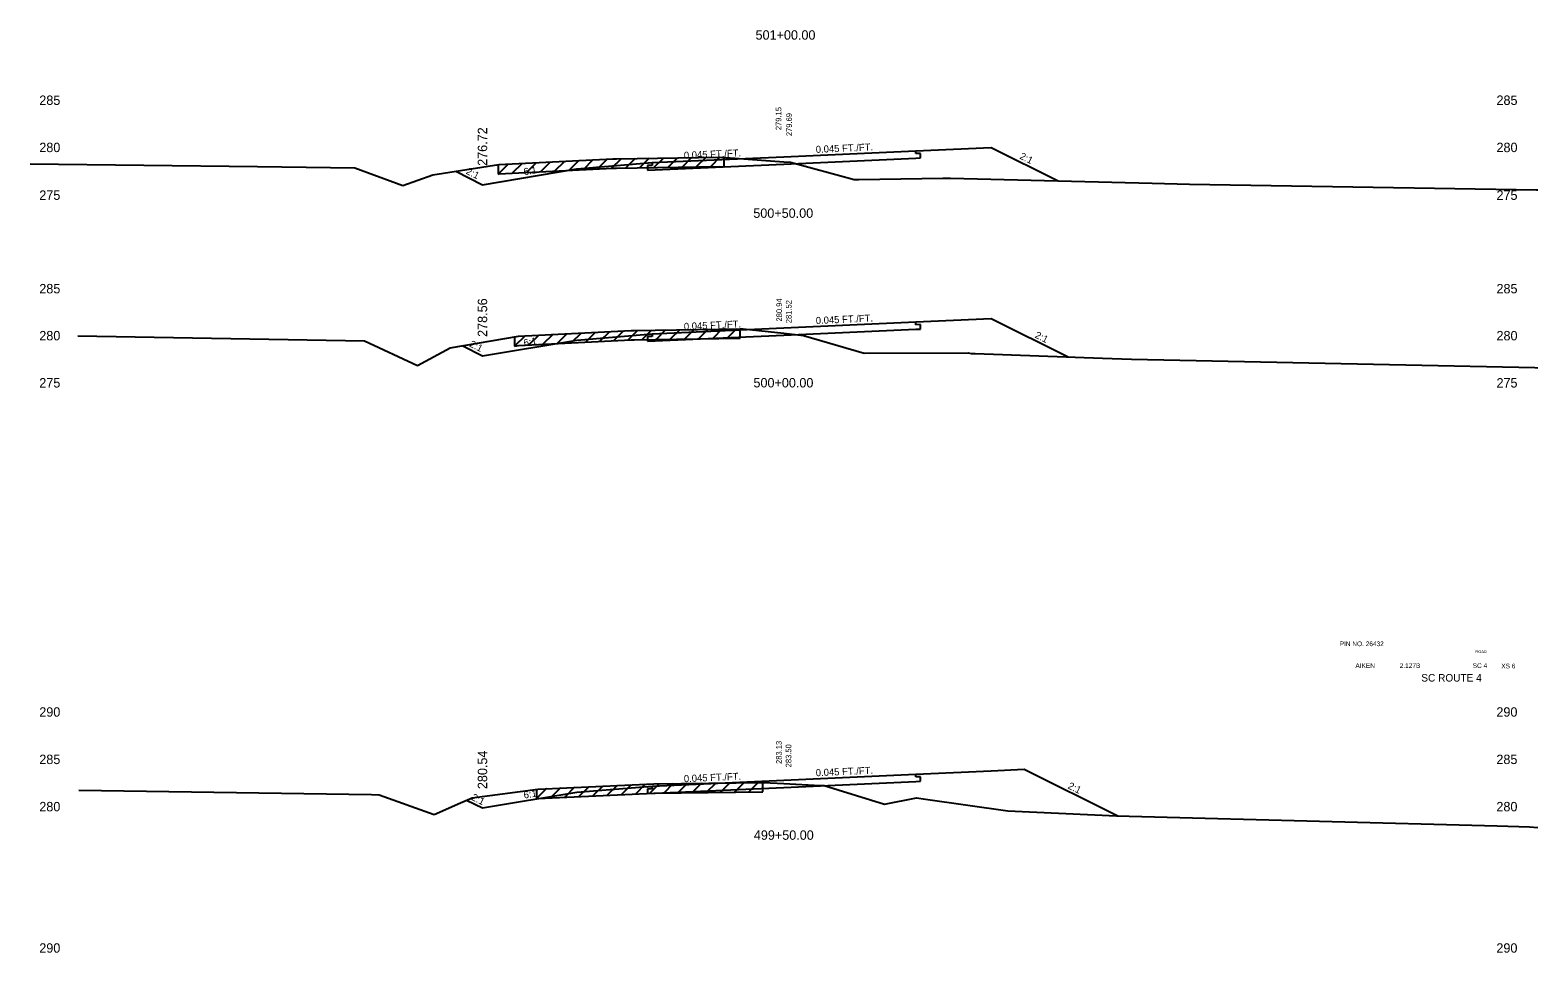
# Model space of a CAD drawing. Extents: x 883 to 1160, y 1002 to 4323.
# Drawn here: x 1000 to 1160, y 1645.2 to 1743.1 of the extents above; entities that cross this region are included whole.
import ezdxf

# ---------------------------------------------------------------- set-up
doc = ezdxf.new("R2010")
doc.units = 0
for name, color, linetype in [('Level 1', 7, 'Continuous'), ('Level 10', 7, 'Continuous'), ('Level 11', 7, 'Continuous'), ('Level 12', 7, 'Continuous'), ('Level 3', 7, 'Continuous'), ('Level 32', 7, 'Continuous'), ('Level 33', 7, 'Continuous'), ('Level 59', 7, 'Continuous'), ('Level 6', 7, 'Continuous'), ('Level 60', 7, 'Continuous'), ('Level 61', 7, 'Continuous'), ('Level 7', 7, 'Continuous')]:
    doc.layers.add(name, color=color, linetype=linetype)

msp = doc.modelspace()

# ---------------------------------------------------------------- linework, layer by layer
at = {"layer": 'Level 11'}
for p, q in [((1094, 1730.02), (1094, 1730.32)), ((1094.5, 1730.04), (1094, 1730.02)), ((1094.5, 1729.56), (1094.5, 1730.04)), ((1094, 1729.54), (1094.5, 1729.56)), ((1094, 1711.85), (1094, 1712.15)), ((1094.5, 1711.87), (1094, 1711.85)), ((1094, 1711.37), (1094.5, 1711.39)), ((1094.5, 1711.39), (1094.5, 1711.87)), ((1094, 1663.83), (1094, 1664.13)), ((1094.5, 1663.85), (1094, 1663.83)), ((1094, 1663.35), (1094.5, 1663.37)), ((1094.5, 1663.37), (1094.5, 1663.85))]:
    msp.add_line(p, q, dxfattribs=at)
at = {"layer": 'Level 12'}
for p, q in [((1065.5, 1728.28), (1080, 1728.91)), ((1066, 1728.76), (1065.5, 1728.76)), ((1065.5, 1728.76), (1065.5, 1728.28)), ((1066, 1729.06), (1066, 1728.76)), ((1080, 1728.91), (1094, 1729.54)), ((1065.5, 1710.11), (1080, 1710.74)), ((1066, 1710.59), (1065.5, 1710.59)), ((1065.5, 1710.59), (1065.5, 1710.11)), ((1066, 1710.89), (1066, 1710.59)), ((1080, 1710.74), (1094, 1711.37)), ((1065.5, 1662.09), (1080, 1662.72)), ((1066, 1662.57), (1065.5, 1662.57)), ((1065.5, 1662.57), (1065.5, 1662.09)), ((1066, 1662.87), (1066, 1662.57)), ((1080, 1662.72), (1094, 1663.35))]:
    msp.add_line(p, q, dxfattribs=at)
at = {"layer": 'Level 59'}
for p, q in [((1066, 1729.06), (1080, 1729.69)), ((1080, 1729.69), (1094, 1730.32)), ((1080, 1711.52), (1094, 1712.15)), ((1066, 1710.89), (1080, 1711.52)), ((1080, 1663.5), (1094, 1664.13)), ((1066, 1662.87), (1080, 1663.5))]:
    msp.add_line(p, q, dxfattribs=at)
at = {"layer": 'Level 6'}
for p, q in [((1094, 1730.32), (1102, 1730.68)), ((1058, 1728.39), (1066, 1729.06)), ((1094, 1712.15), (1102, 1712.51)), ((1058, 1710.22), (1066, 1710.89)), ((1094, 1664.13), (1102, 1664.49)), ((1102, 1664.49), (1105.5, 1664.65)), ((1058, 1662.2), (1066, 1662.87))]:
    msp.add_line(p, q, dxfattribs=at)
at = {"layer": 'Level 60'}
for p, q in [((1062.22, 1729.47), (1073.11, 1729.64)), ((1073.11, 1729.64), (1073.81, 1729.62)), ((1073.81, 1729.62), (1080, 1729.15)), ((1000, 1728.92), (1024.13, 1728.65)), ((1024.13, 1728.65), (1034.44, 1728.51)), ((1034.44, 1728.51), (1039.55, 1726.65)), ((1042.74, 1727.76), (1049.73, 1728.86)), ((1049.73, 1728.86), (1061.84, 1729.46)), ((1061.84, 1729.46), (1062.22, 1729.47)), ((1080, 1729.15), (1080.68, 1729.1)), ((1080.68, 1729.1), (1087.44, 1727.28)), ((1039.55, 1726.65), (1042.74, 1727.76)), ((1087.44, 1727.28), (1087.94, 1727.28)), ((1087.94, 1727.28), (1096.85, 1727.43)), ((1096.85, 1727.43), (1097.68, 1727.4)), ((1097.68, 1727.4), (1119.07, 1726.88)), ((1119.07, 1726.88), (1123.03, 1726.79)), ((1123.03, 1726.79), (1159.87, 1726.19)), ((1159.87, 1726.19), (1160, 1726.18)), ((1005.06, 1710.68), (1035.47, 1710.13)), ((1044.57, 1709.38), (1051.82, 1710.65)), ((1051.82, 1710.65), (1063.78, 1711.23)), ((1063.78, 1711.23), (1064.1, 1711.24)), ((1064.1, 1711.24), (1075.33, 1711.43)), ((1075.33, 1711.43), (1075.66, 1711.43)), ((1075.66, 1711.43), (1080, 1710.94)), ((1080, 1710.94), (1082.07, 1710.72)), ((1082.07, 1710.72), (1088.5, 1708.83)), ((1035.47, 1710.13), (1041.1, 1707.53)), ((1041.1, 1707.53), (1044.57, 1709.38)), ((1088.5, 1708.83), (1099.56, 1708.86)), ((1099.56, 1708.86), (1099.86, 1708.81)), ((1099.86, 1708.81), (1100.3, 1708.79)), ((1100.3, 1708.79), (1113.79, 1708.29)), ((1113.79, 1708.29), (1116.87, 1708.21)), ((1116.87, 1708.21), (1159.68, 1707.3)), ((1159.68, 1707.3), (1160, 1707.29)), ((1005.18, 1662.44), (1036.24, 1661.97)), ((1046.89, 1661.63), (1053.87, 1662.55)), ((1053.87, 1662.55), (1066.19, 1663.11)), ((1066.19, 1663.11), (1077.82, 1663.24)), ((1077.82, 1663.24), (1080, 1663.13)), ((1080, 1663.13), (1083.84, 1662.93)), ((1083.84, 1662.93), (1084.25, 1662.91)), ((1084.25, 1662.91), (1090.66, 1660.94)), ((1036.24, 1661.97), (1037.05, 1661.95)), ((1037.05, 1661.95), (1042.87, 1659.86)), ((1042.87, 1659.86), (1045.68, 1661.1)), ((1045.68, 1661.1), (1046.89, 1661.63)), ((1090.66, 1660.94), (1094.06, 1661.6)), ((1094.06, 1661.6), (1095.01, 1661.49)), ((1095.01, 1661.49), (1103.74, 1660.25)), ((1103.74, 1660.25), (1115.3, 1659.69)), ((1115.3, 1659.69), (1117.98, 1659.63)), ((1117.98, 1659.63), (1155.69, 1658.65)), ((1155.69, 1658.65), (1159.12, 1658.54)), ((1159.12, 1658.54), (1160, 1658.46))]:
    msp.add_line(p, q, dxfattribs=at)
at = {"layer": 'Level 61'}
for p, q in [((1071.7, 1729.62), (1070.69, 1728.61)), ((1073.2, 1729.64), (1072.19, 1728.63)), ((1073.64, 1728.63), (1073.64, 1729.63)), ((1050.72, 1728.91), (1049.65, 1727.85)), ((1049.65, 1728.85), (1049.65, 1727.85)), ((1049.73, 1727.86), (1061.84, 1728.46)), ((1052.21, 1728.98), (1051.16, 1727.93)), ((1053.71, 1729.05), (1052.66, 1728)), ((1055.21, 1729.13), (1054.16, 1728.08)), ((1056.72, 1729.2), (1055.66, 1728.15)), ((1058.22, 1729.28), (1057.17, 1728.23)), ((1059.72, 1729.35), (1058.67, 1728.3)), ((1061.22, 1729.43), (1060.17, 1728.37)), ((1062.71, 1729.48), (1061.67, 1728.45)), ((1061.84, 1728.46), (1062.22, 1728.47)), ((1062.22, 1728.47), (1073.11, 1728.64)), ((1064.19, 1729.5), (1063.17, 1728.49)), ((1065.69, 1729.53), (1064.68, 1728.51)), ((1067.2, 1729.55), (1066.18, 1728.54)), ((1068.7, 1729.57), (1067.68, 1728.56)), ((1070.2, 1729.6), (1069.18, 1728.58)), ((1073.11, 1728.64), (1073.64, 1728.63)), ((1049.65, 1727.85), (1049.73, 1727.86)), ((1052.52, 1710.68), (1051.41, 1709.58)), ((1051.41, 1710.58), (1051.41, 1709.58)), ((1053.97, 1710.75), (1052.91, 1709.7)), ((1055.47, 1710.82), (1054.41, 1709.77)), ((1056.97, 1710.9), (1055.92, 1709.85)), ((1058.47, 1710.97), (1057.42, 1709.92)), ((1059.97, 1711.04), (1058.92, 1709.99)), ((1061.47, 1711.11), (1060.42, 1710.06)), ((1062.97, 1711.19), (1061.92, 1710.14)), ((1064.46, 1711.25), (1063.42, 1710.21)), ((1064.1, 1710.24), (1075.33, 1710.43)), ((1065.94, 1711.27), (1064.92, 1710.25)), ((1067.44, 1711.3), (1066.43, 1710.28)), ((1068.94, 1711.32), (1067.93, 1710.3)), ((1070.45, 1711.35), (1069.43, 1710.33)), ((1071.95, 1711.37), (1070.93, 1710.35)), ((1073.45, 1711.4), (1072.43, 1710.38)), ((1074.95, 1711.42), (1073.93, 1710.4)), ((1075.33, 1710.43), (1075.36, 1710.43)), ((1075.36, 1710.43), (1075.36, 1711.43)), ((1051.41, 1709.58), (1051.82, 1709.65)), ((1051.82, 1709.65), (1063.78, 1710.23)), ((1063.78, 1710.23), (1064.1, 1710.24)), ((1054.79, 1662.59), (1053.73, 1661.53)), ((1053.73, 1662.53), (1053.73, 1661.53)), ((1056.28, 1662.66), (1055.23, 1661.61)), ((1057.78, 1662.73), (1056.73, 1661.68)), ((1059.28, 1662.79), (1058.23, 1661.75)), ((1060.78, 1662.86), (1059.73, 1661.81)), ((1062.28, 1662.93), (1061.23, 1661.88)), ((1063.78, 1663), (1062.73, 1661.95)), ((1065.28, 1663.06), (1064.23, 1662.02)), ((1066.76, 1663.11), (1065.73, 1662.08)), ((1068.24, 1663.13), (1067.23, 1662.12)), ((1069.74, 1663.15), (1068.73, 1662.13)), ((1071.25, 1663.16), (1070.23, 1662.15)), ((1072.75, 1663.18), (1071.73, 1662.17)), ((1074.25, 1663.2), (1073.23, 1662.18)), ((1075.75, 1663.21), (1074.73, 1662.2)), ((1077.25, 1663.23), (1076.23, 1662.22)), ((1077.75, 1662.24), (1077.75, 1663.24)), ((1053.73, 1661.53), (1053.87, 1661.55)), ((1053.87, 1661.55), (1066.19, 1662.11)), ((1066.19, 1662.11), (1077.75, 1662.24))]:
    msp.add_line(p, q, dxfattribs=at)
at = {"layer": 'Level 7'}
for p, q in [((1102, 1730.68), (1109.11, 1727.12)), ((1045.16, 1728.14), (1048, 1726.72)), ((1048, 1726.72), (1058, 1728.39)), ((1102, 1712.51), (1110.17, 1708.43)), ((1045.9, 1709.61), (1048, 1708.56)), ((1048, 1708.56), (1058, 1710.22)), ((1105.5, 1664.65), (1115.41, 1659.69)), ((1046.32, 1661.38), (1048, 1660.54)), ((1048, 1660.54), (1058, 1662.2))]:
    msp.add_line(p, q, dxfattribs=at)

# ---------------------------------------------------------------- texts
at = {"layer": 'Level 1'}
for s, height, p in [('501+00.00', 1, (1076.98, 1742.12)), ('500+50.00', 1, (1076.74, 1723.2)), ('500+00.00', 1, (1076.76, 1705.19)), ('PIN NO. 26432', 0.5, (1138.97, 1677.72)), ('AIKEN', 0.5, (1140.64, 1675.4)), (' 2.127B', 0.5, (1145.15, 1675.4)), ('SC 4', 0.5, (1153.09, 1675.4)), ('XS 6', 0.5, (1156.12, 1675.36)), ('SC ROUTE 4', 0.8, (1147.63, 1673.96)), ('499+50.00', 1, (1076.8, 1657.16))]:
    msp.add_text(s, height=height, dxfattribs=at).set_placement(p)
at = {"layer": 'Level 10'}
for s, p in [('279.15', (1079.72, 1732.51)), ('280.94', (1079.79, 1712.19)), ('283.13', (1079.76, 1665.21))]:
    msp.add_text(s, height=0.6, rotation=90, dxfattribs=at).set_placement(p)
at = {"layer": 'Level 3'}
for s, height, p in [(' 285', 1, (1000.6, 1735.19)), (' 285', 1, (1155.24, 1735.19)), (' 280', 1, (1000.6, 1730.18)), (' 280', 1, (1155.24, 1730.18)), (' 275', 1, (1000.6, 1725.11)), (' 275', 1, (1155.24, 1725.11)), (' 285', 1, (1000.6, 1715.18)), (' 285', 1, (1155.24, 1715.18)), (' 280', 1, (1000.6, 1710.19)), (' 280', 1, (1155.24, 1710.19)), (' 275', 1, (1000.6, 1705.18)), (' 275', 1, (1155.24, 1705.18)), ('ROAD', 0.3, (1153.38, 1676.99)), (' 290', 1, (1000.6, 1670.23)), (' 290', 1, (1155.23, 1670.23)), (' 285', 1, (1000.6, 1665.2)), (' 285', 1, (1155.23, 1665.2)), (' 280', 1, (1000.6, 1660.18)), (' 280', 1, (1155.23, 1660.18)), (' 290', 1, (1000.6, 1645.17)), (' 290', 1, (1155.23, 1645.17))]:
    msp.add_text(s, height=height, dxfattribs=at).set_placement(p)
at = {"layer": 'Level 32'}
for s, rotation, p in [('0.045 FT./FT.', 2.5766, (1069.39, 1729.46)), ('0.045 FT./FT.', 2.5766, (1083.39, 1730.09)), ('2:1', 333.435, (1104.94, 1729.51)), ('2:1', 333.435, (1046.19, 1727.91)), ('6:1', 9.4623, (1052.43, 1727.72)), ('0.045 FT./FT.', 2.5766, (1069.39, 1711.29)), ('0.045 FT./FT.', 2.5766, (1083.39, 1711.92)), ('6:1', 9.4623, (1052.43, 1709.55)), ('2:1', 333.435, (1106.56, 1710.51)), ('2:1', 333.435, (1046.55, 1709.56)), ('0.045 FT./FT.', 2.5766, (1069.39, 1663.27)), ('0.045 FT./FT.', 2.5766, (1083.39, 1663.9)), ('6:1', 9.4623, (1052.43, 1661.53)), ('2:1', 333.435, (1110.06, 1662.65)), ('2:1', 333.435, (1046.76, 1661.43))]:
    msp.add_text(s, height=0.75, rotation=rotation, dxfattribs=at).set_placement(p)
at = {"layer": 'Level 33'}
for s, p in [('276.72', (1048.5, 1728.72)), ('278.56', (1048.5, 1710.56)), ('280.54', (1048.5, 1662.54))]:
    msp.add_text(s, height=1, rotation=90, dxfattribs=at).set_placement(p)
at = {"layer": 'Level 59'}
for s, p in [(' 279.69', (1080.84, 1731.65)), (' 281.52', (1080.8, 1711.79)), (' 283.50', (1080.78, 1664.63))]:
    msp.add_text(s, height=0.6, rotation=90, dxfattribs=at).set_placement(p)

doc.saveas('drawing.dxf')
